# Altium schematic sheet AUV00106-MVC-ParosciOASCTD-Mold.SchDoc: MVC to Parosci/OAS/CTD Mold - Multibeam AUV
size Tabloid; Organization: Monterey Bay Aquarium Research Institute; Address1: 7700 Sandholdt Rd; Address2: Moss Landing, CA 95039-9644; DocumentNumber: AUV00106; Revision: 1; SheetNumber: 1; SheetTotal: 1; CompanyName: MBARI; Engineer: Mark Sibenac
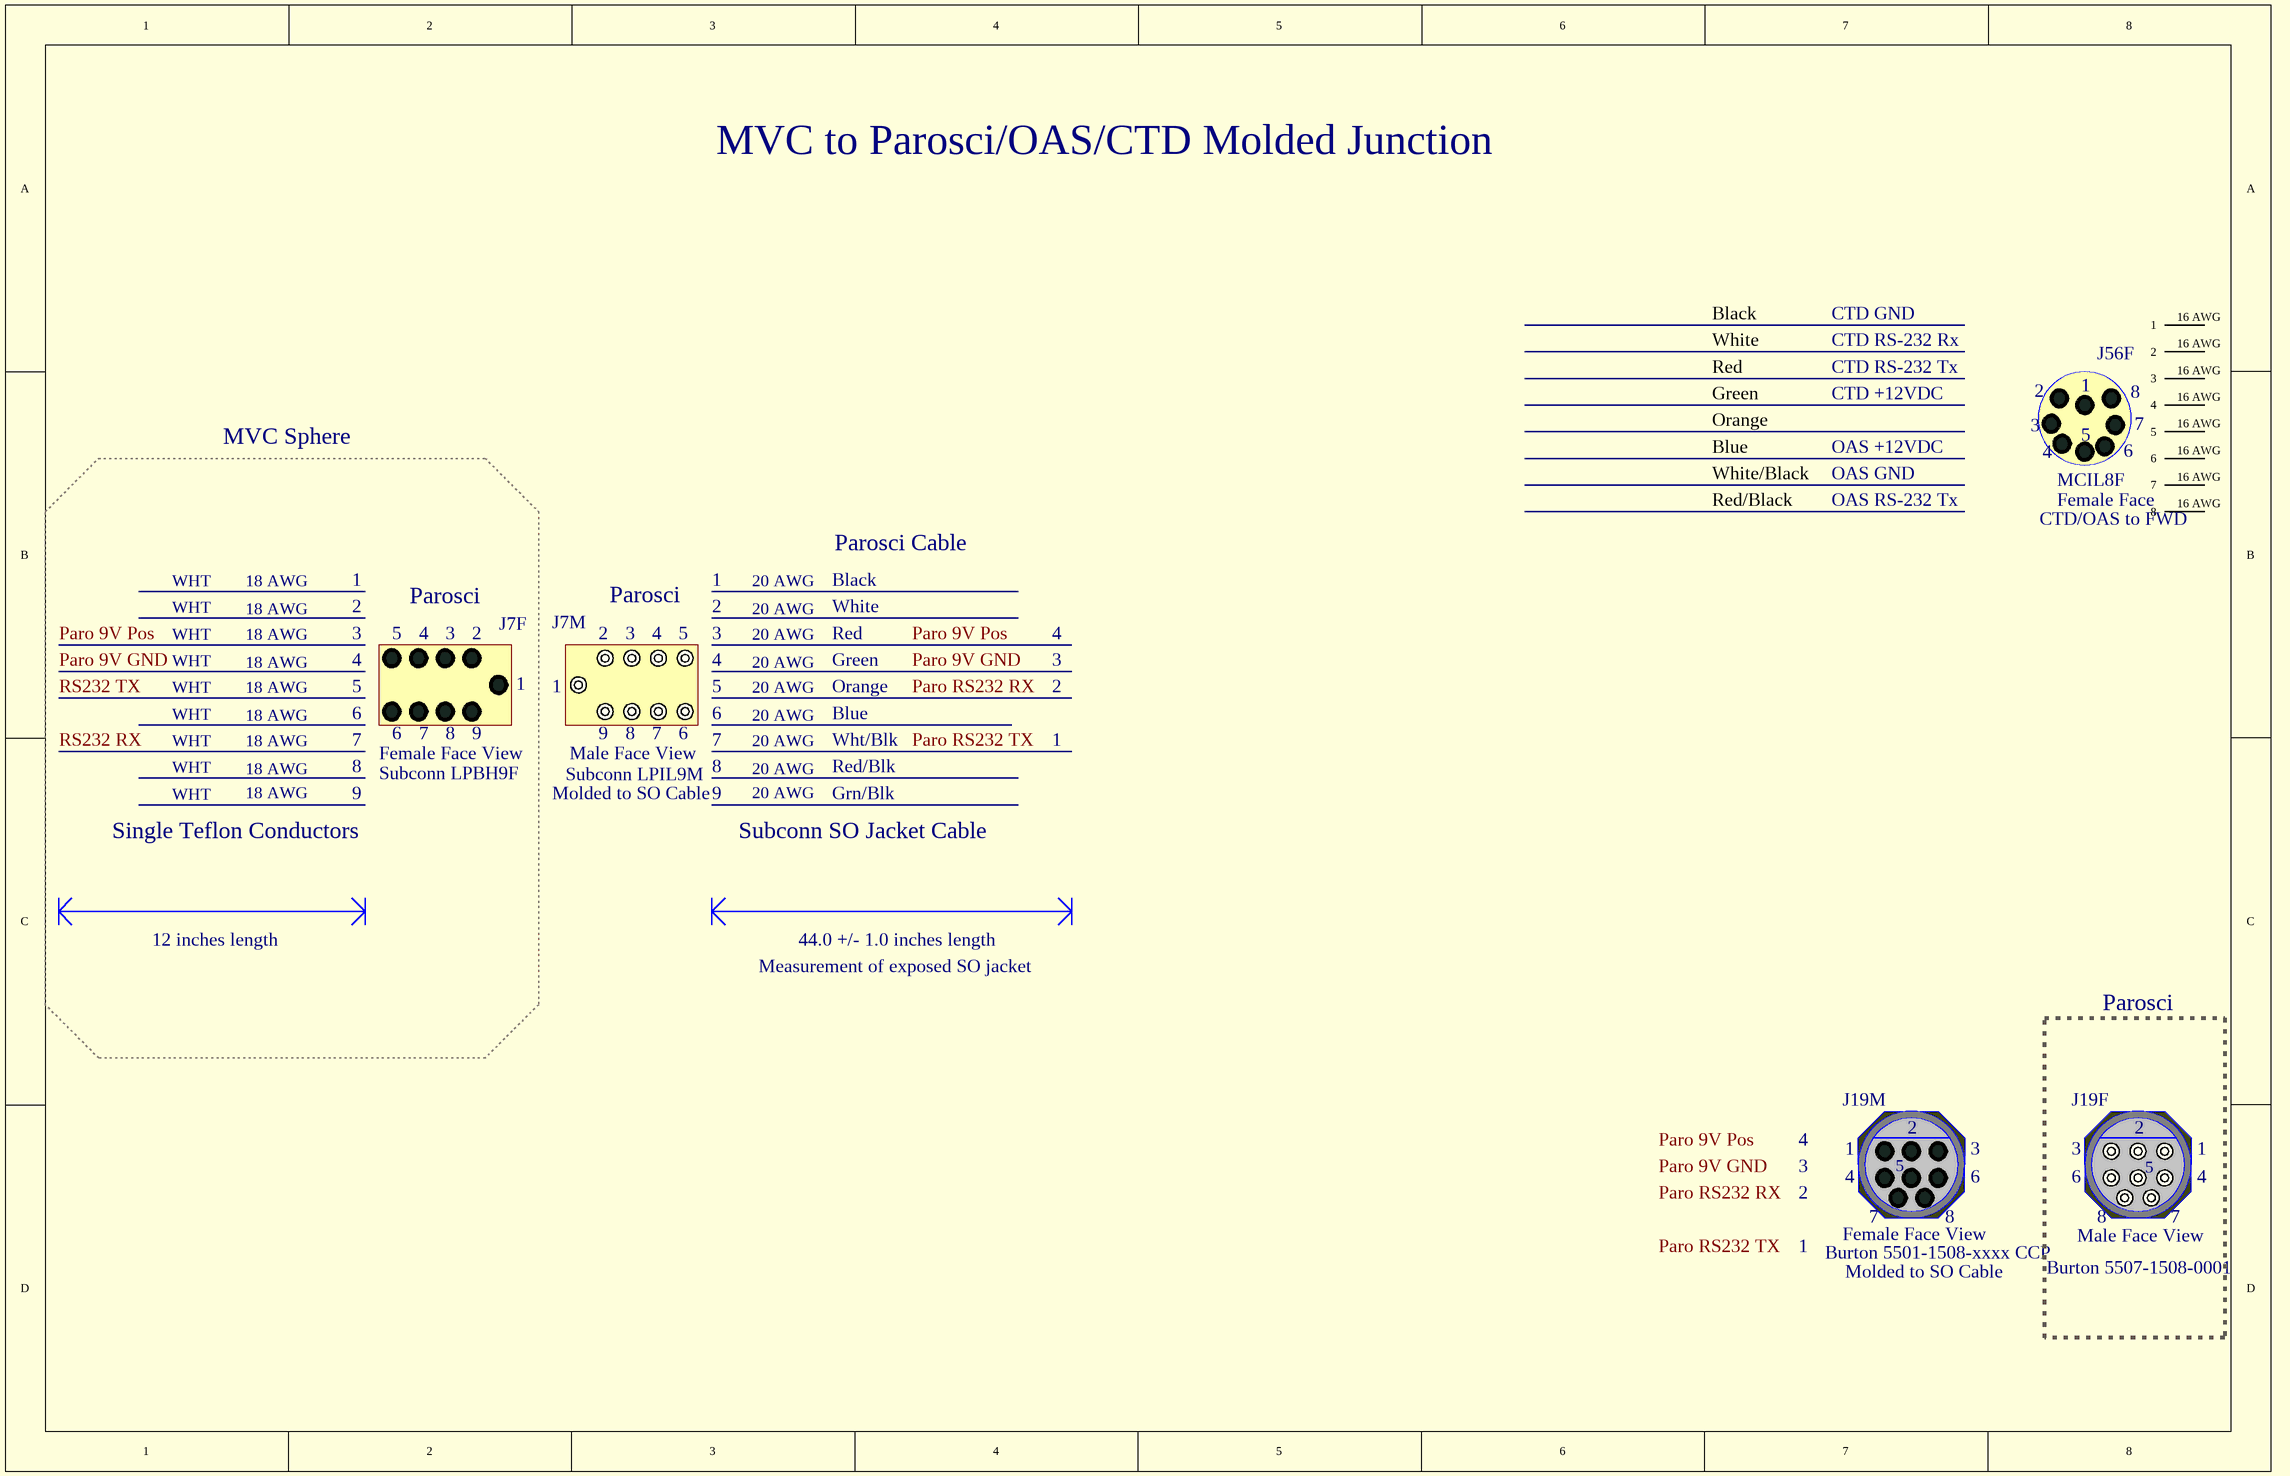
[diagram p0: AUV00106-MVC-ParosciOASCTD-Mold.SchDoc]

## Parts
J7F  LPBH9F: Subconn LPBH9F
J7M  LPIL9M: Subconn LPIL9M
J19F  Burton 5507-1508-0001
J19M  Burton 5501-1508-xxxx CCP
J56F  MCIL8F  DescSheet: CTD/OAS to FWD  View: Female Face

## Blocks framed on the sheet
Parosci: J19F

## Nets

Not connected (* = marked no-connect by the designer): J56F 16 AWG(1)

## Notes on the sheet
- MVC to Parosci/OAS/CTD Molded Junction
- Black
- White
- CTD RS-232 Rx
- CTD GND
- Red
- Green
- Orange
- CTD RS-232 Tx
- CTD +12VDC
- MVC Sphere
- Blue
- White/Black
- OAS GND
- OAS +12VDC
- Parosci Cable
- Red/Black
- OAS RS-232 Tx
- WHT
- 18 AWG
- 1
- 2
- Parosci
- 20 AWG
- 3
- 4
- 5
- 6
- 7
- Wht/Blk
- 8
- 9
- Molded to SO Cable
- Red/Blk
- Grn/Blk
- Single Teflon Conductors
- Subconn SO Jacket Cable
- 12 inches length
- 44.0 +/- 1.0 inches length
- Measurement of exposed SO jacket
- Labels drawn without touching a wire or pin: Paro 9V GND, Paro 9V Pos, Paro RS232 RX, Paro RS232 TX

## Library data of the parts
J7F = SUBCONN-LPXX9F: Subconn LPxx9F Connector; LPIL9F: Subconn LPIL9F
J7M = SUBCONN-LPXX9M: Subconn LPxx9F Connector
J19F = BURTON-5507-1508-0001: Burton 8 Pin Male BH Connector
J19M = BURTON-5999-1007-C004: Burton 8 Socket Female IL Connector
J56F = SUBCONN-MCxx8F: Subconn MCIL8F Connector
